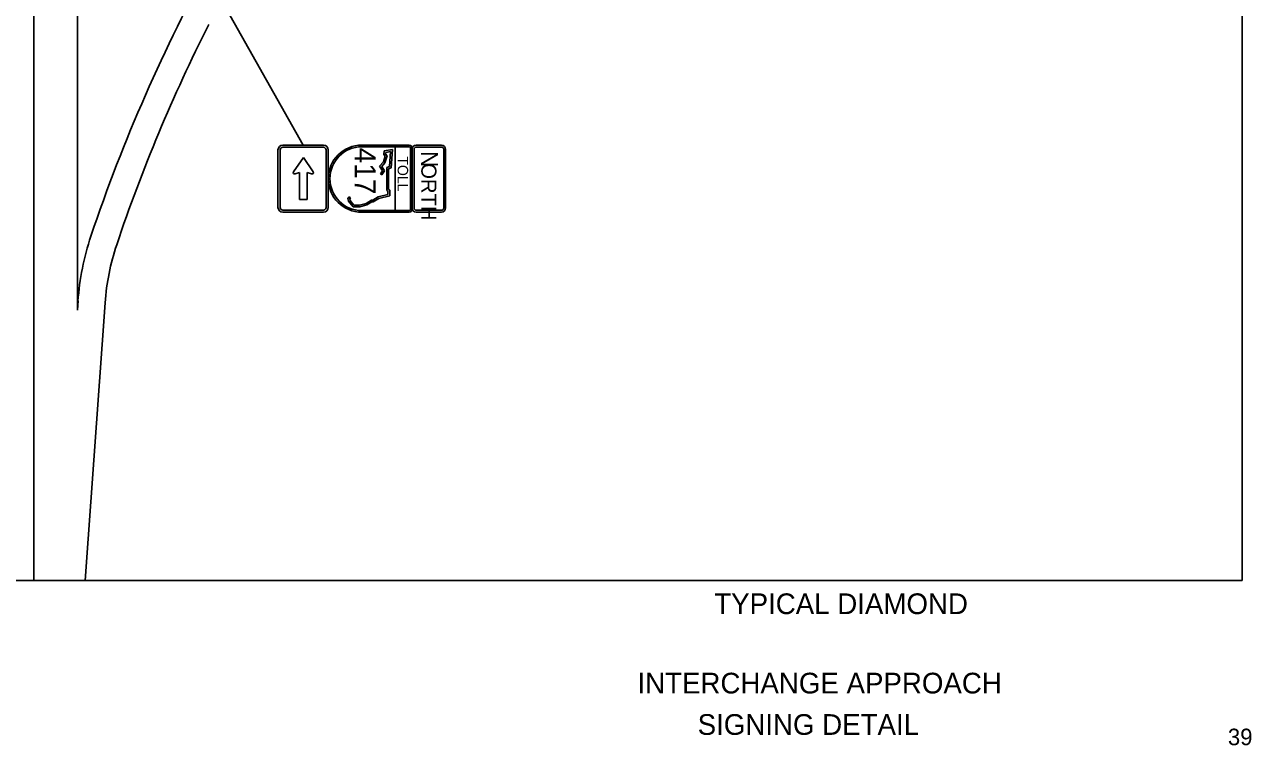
# Model space of a CAD drawing. Extents: x -830008.4 to -829992.7, y 1290284.1 to 1290294.4.
# Drawn here: x -830000.13 to -829992.72, y 1290284.33 to 1290288.68 of the extents above; entities that cross this region are included whole.
import ezdxf

# ---------------------------------------------------------------- set-up
doc = ezdxf.new("R2010")
doc.units = 0
for name, color, linetype in [('1', 7, 'Continuous'), ('SheetBorder_dp', 7, 'Continuous'), ('SheetLines_dp', 7, 'Continuous'), ('TextLabel', 7, 'Continuous'), ('TextNotes', 7, 'Continuous')]:
    doc.layers.add(name, color=color, linetype=linetype)

msp = doc.modelspace()

# ---------------------------------------------------------------- linework, layer by layer
at = {"layer": '1'}
for p, q in [((-830000.0719, 1290294.228), (-830000.0719, 1290285.328)), ((-829999.2537, 1290289.3928), (-829998.4458, 1290287.9567)), ((-829999.8091, 1290288.9868), (-829999.8096, 1290286.9607)), ((-829999.8056, 1290287.0168), (-829999.8096, 1290286.9607)), ((-829999.642, 1290287.0051), (-829999.7619, 1290285.328))]:
    msp.add_line(p, q, dxfattribs=at)
for centre, radius, start, end in [((-829990.0742, 1290284.1655), 10.183, 151.15873, 161.43615), ((-829990.0742, 1290284.1655), 10.0189, 153.18648, 161.43615), ((-829998.2289, 1290286.9041), 1.5807, 161.43615, 176.0167), ((-829998.2289, 1290286.9041), 1.4167, 161.43615, 175.91011)]:
    msp.add_arc(centre, radius, start, end, dxfattribs=at)
at = {"layer": 'SheetBorder_dp'}
for p, q in [((-829997.9584, 1290287.901), (-829997.9558, 1290287.9219)), ((-829997.9494, 1290287.8895), (-829997.9584, 1290287.901)), ((-829997.9558, 1290287.9219), (-829997.9058, 1290287.9297)), ((-829997.9463, 1290287.9127), (-829997.9474, 1290287.9041)), ((-829997.9474, 1290287.9041), (-829997.9376, 1290287.8916)), ((-829997.9173, 1290287.9173), (-829997.9463, 1290287.9127)), ((-829997.9242, 1290287.8278), (-829997.9173, 1290287.9173)), ((-829997.9058, 1290287.9297), (-829997.9142, 1290287.8204)), ((-829998.4442, 1290287.8823), (-829998.5034, 1290287.796)), ((-829998.385, 1290287.796), (-829998.4442, 1290287.8823)), ((-829997.9836, 1290287.8302), (-829997.9606, 1290287.8549)), ((-829997.9665, 1290287.8011), (-829997.9836, 1290287.8302)), ((-829997.9513, 1290287.8495), (-829997.9705, 1290287.8287)), ((-829997.9705, 1290287.8287), (-829997.954, 1290287.8007)), ((-829997.9606, 1290287.8549), (-829997.9494, 1290287.8895)), ((-829997.9376, 1290287.8916), (-829997.9513, 1290287.8495)), ((-829997.9405, 1290287.8215), (-829997.9242, 1290287.8278)), ((-829997.9405, 1290287.6832), (-829997.9405, 1290287.8215)), ((-829997.9142, 1290287.8204), (-829997.9299, 1290287.8142)), ((-829998.4938, 1290287.7828), (-829998.467, 1290287.7908)), ((-829998.467, 1290287.7908), (-829998.467, 1290287.6284)), ((-829998.4214, 1290287.6284), (-829998.4214, 1290287.7908)), ((-829998.4214, 1290287.7908), (-829998.3946, 1290287.7828)), ((-829997.9782, 1290287.7837), (-829997.9665, 1290287.8011)), ((-829997.9695, 1290287.7778), (-829997.9782, 1290287.7837)), ((-829997.954, 1290287.8007), (-829997.9695, 1290287.7778)), ((-829997.9299, 1290287.8142), (-829997.9299, 1290287.6888)), ((-829997.9335, 1290287.6785), (-829997.9405, 1290287.6832)), ((-829997.9335, 1290287.6587), (-829997.9335, 1290287.6785)), ((-829997.9299, 1290287.6888), (-829997.923, 1290287.6841)), ((-829997.923, 1290287.6841), (-829997.923, 1290287.6503)), ((-829998.467, 1290287.6284), (-829998.4214, 1290287.6284)), ((-829998.1758, 1290287.6348), (-829998.1686, 1290287.6452)), ((-829998.1718, 1290287.6184), (-829998.1758, 1290287.6348)), ((-829998.1435, 1290287.5839), (-829998.1718, 1290287.6184)), ((-829998.1686, 1290287.6452), (-829998.1599, 1290287.6392)), ((-829998.1599, 1290287.6392), (-829998.1644, 1290287.6327)), ((-829998.1644, 1290287.6327), (-829998.1622, 1290287.6232)), ((-829998.1622, 1290287.6232), (-829998.1385, 1290287.5944)), ((-829998.1053, 1290287.5944), (-829998.0658, 1290287.6052)), ((-829998.0658, 1290287.6052), (-829998.0335, 1290287.6248)), ((-829998.0306, 1290287.6143), (-829998.0615, 1290287.5954)), ((-829998.0335, 1290287.6248), (-829998.0251, 1290287.6248)), ((-829998.0221, 1290287.6143), (-829998.0306, 1290287.6143)), ((-829998.0251, 1290287.6248), (-829997.9928, 1290287.6449)), ((-829997.9887, 1290287.6351), (-829998.0221, 1290287.6143)), ((-829997.9928, 1290287.6449), (-829997.9335, 1290287.6587)), ((-829997.923, 1290287.6503), (-829997.9887, 1290287.6351)), ((-829998.1039, 1290287.5839), (-829998.1435, 1290287.5839)), ((-829998.1385, 1290287.5944), (-829998.1053, 1290287.5944)), ((-829998.0615, 1290287.5954), (-829998.1039, 1290287.5839))]:
    msp.add_line(p, q, dxfattribs=at)
for points in [[(-829998.5977, 1290287.5807), (-829998.5977, 1290287.9278)], [(-829998.5844, 1290287.5807), (-829998.5844, 1290287.9278)], [(-829998.5687, 1290287.9567), (-829998.3228, 1290287.9567)], [(-829998.5687, 1290287.9435), (-829998.3228, 1290287.9435)], [(-829998.3072, 1290287.9278), (-829998.3072, 1290287.5807)], [(-829998.2939, 1290287.9278), (-829998.2939, 1290287.5807)], [(-829998.0914, 1290287.9567), (-829997.8045, 1290287.9567)], [(-829998.0914, 1290287.9466), (-829997.8045, 1290287.9466)], [(-829997.8889, 1290287.9466), (-829997.8889, 1290287.5619)], [(-829997.7978, 1290287.9399), (-829997.7978, 1290287.5686)], [(-829997.7877, 1290287.9399), (-829997.7877, 1290287.5686)], [(-829997.7877, 1290287.577), (-829997.7877, 1290287.9314)], [(-829997.776, 1290287.577), (-829997.776, 1290287.9314)], [(-829997.7623, 1290287.9567), (-829997.6105, 1290287.9567)], [(-829997.7623, 1290287.9451), (-829997.6105, 1290287.9451)], [(-829997.5968, 1290287.9314), (-829997.5968, 1290287.577)], [(-829997.5852, 1290287.9314), (-829997.5852, 1290287.577)], [(-829998.3228, 1290287.565), (-829998.5687, 1290287.565)], [(-829998.3228, 1290287.5517), (-829998.5687, 1290287.5517)], [(-829997.8045, 1290287.5619), (-829998.0914, 1290287.5619)], [(-829997.8045, 1290287.5517), (-829998.0914, 1290287.5517)], [(-829997.6105, 1290287.5633), (-829997.7623, 1290287.5633)], [(-829997.6105, 1290287.5517), (-829997.7623, 1290287.5517)]]:
    msp.add_lwpolyline(points, dxfattribs=at)
for centre, radius, start, end in [((-829998.5687, 1290287.9278), 0.0289, 90, 180), ((-829998.5687, 1290287.9278), 0.0157, 90, 180), ((-829998.3228, 1290287.9278), 0.0289, 360, 90), ((-829998.3228, 1290287.9278), 0.0157, 360, 89.9456), ((-829998.0914, 1290287.7542), 0.2025, 90, 270), ((-829998.0914, 1290287.7542), 0.1924, 90, 270), ((-829997.8045, 1290287.9399), 0.0169, 0, 90), ((-829997.8045, 1290287.9399), 0.00675, 0, 90), ((-829997.7623, 1290287.9314), 0.0253, 90, 180), ((-829997.7623, 1290287.9314), 0.0137, 90, 180), ((-829997.6105, 1290287.9314), 0.0253, 0, 90), ((-829997.6105, 1290287.9314), 0.0137, 0, 90), ((-829998.4963, 1290287.7911), 0.00868, 145.51192, 286.64431), ((-829998.3921, 1290287.7911), 0.00868, 253.35571, 34.48807), ((-829998.5687, 1290287.5807), 0.0289, 180, 270), ((-829998.5687, 1290287.5807), 0.0157, 180, 270), ((-829998.3228, 1290287.5807), 0.0289, 270, 360), ((-829998.3228, 1290287.5807), 0.0157, 270.0544, 360), ((-829997.8045, 1290287.5686), 0.0169, 270, 0), ((-829997.8045, 1290287.5686), 0.00675, 270, 0), ((-829997.7623, 1290287.577), 0.0253, 180, 270), ((-829997.7623, 1290287.577), 0.0137, 180, 270), ((-829997.6105, 1290287.577), 0.0253, 270, 0), ((-829997.6105, 1290287.577), 0.0137, 270, 0)]:
    msp.add_arc(centre, radius, start, end, dxfattribs=at)
at = {"layer": 'SheetLines_dp'}
msp.add_lwpolyline([(-830007.4742, 1290294.228), (-829992.7742, 1290294.228), (-829992.7742, 1290285.328), (-830007.4742, 1290285.328)], close=True, dxfattribs=at)

# ---------------------------------------------------------------- texts
at = {"layer": 'SheetBorder_dp'}
for s, height, p in [('417', 0.12656, (-829998.1336, 1290287.9416)), ('N', 0.1013, (-829997.733, 1290287.9212)), ('TOLL', 0.06328, (-829997.875, 1290287.8887)), ('ORTH', 0.09113, (-829997.7318, 1290287.8473))]:
    msp.add_text(s, height=height, rotation=270, dxfattribs=at).set_placement(p)
at = {"layer": 'TextLabel'}
for s, p in [('TYPICAL DIAMOND', (-829995.9625, 1290285.1249)), ('  INTERCHANGE APPROACH  ', (-829996.5194, 1290284.6457)), ('     SIGNING DETAIL     ', (-829996.2949, 1290284.3957))]:
    msp.add_text(s, height=0.125, dxfattribs=at).set_placement(p)
at = {"layer": 'TextNotes'}
msp.add_text('39', height=0.1, dxfattribs=at).set_placement((-829992.8599, 1290284.3332))

doc.saveas('drawing.dxf')
